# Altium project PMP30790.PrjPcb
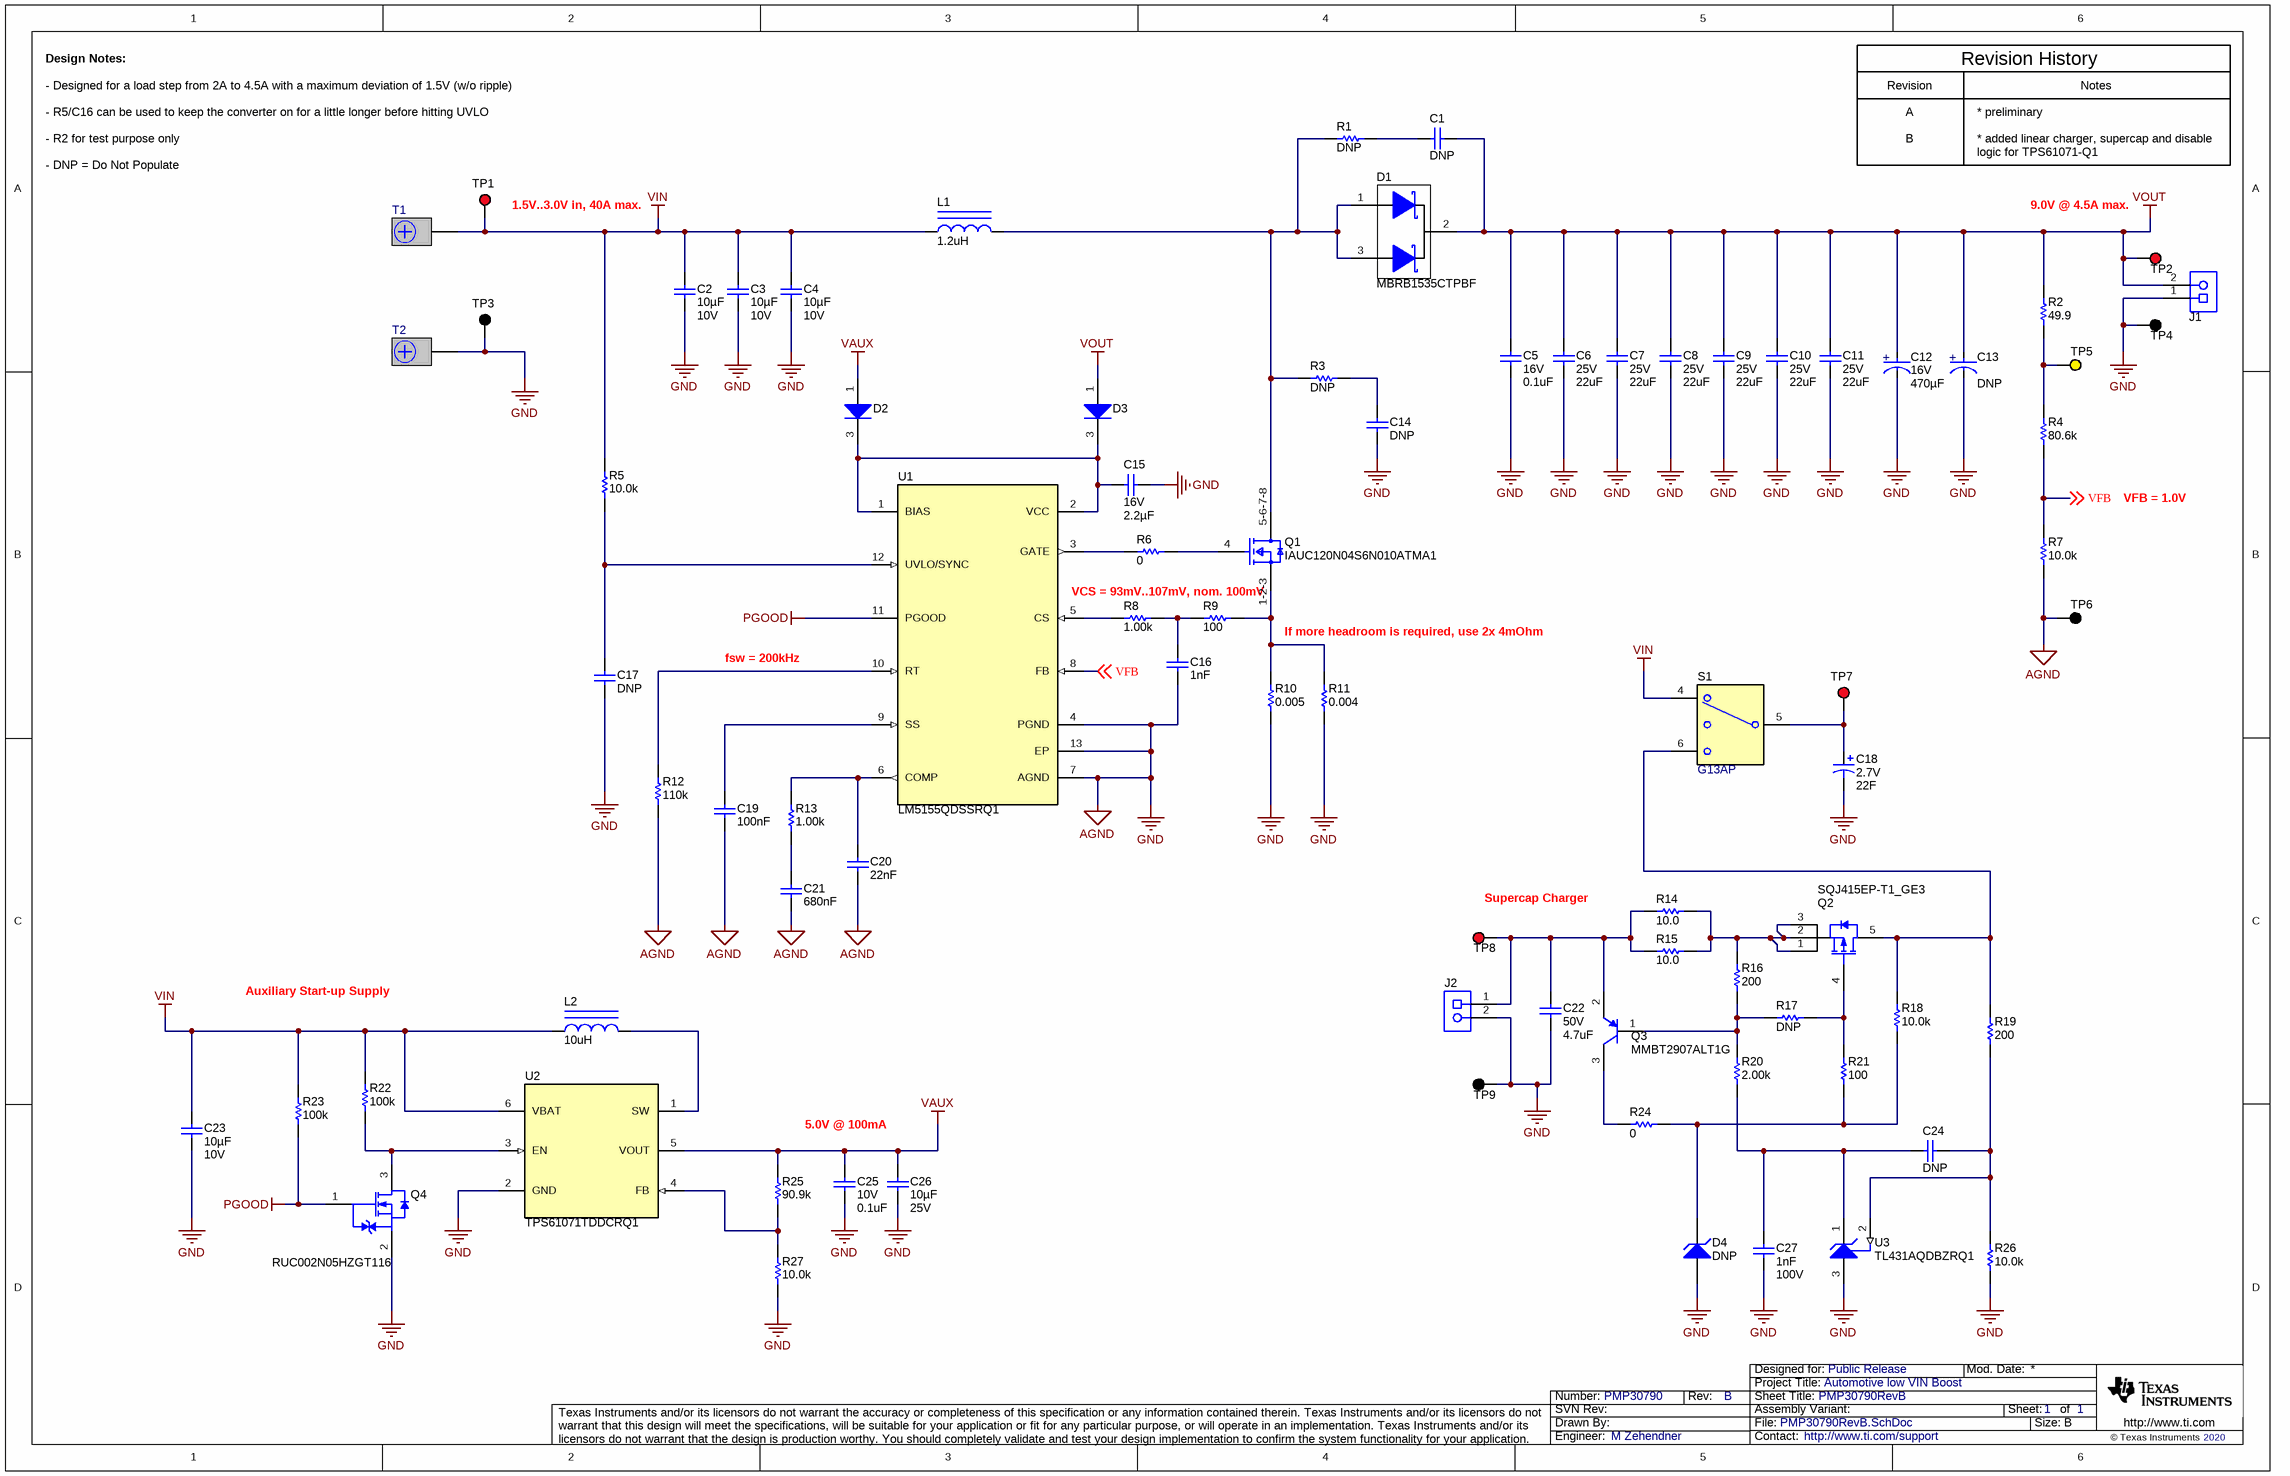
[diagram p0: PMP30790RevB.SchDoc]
CopyrightYear: 2020; PCB_Rev: A; PRJ_Customer: Public Release; PRJ_Engineer: M Zehendner; PRJ_Number: PMP30790; PRJ_Title: Automotive low VIN Boost; SCH_Rev: B; TechSupport: http://www.ti.com/support; TID: N/A
1 sheet, 81 parts. Net scope: global (net labels, ports and power ports of the same name join across sheets).
Board file: PMP30790_PCB.PcbDoc

## Sheet PMP30790RevB.SchDoc: PMP30790RevB
size 431 x 279 mm; DocumentNumber: 1; Revision: A; SheetNumber: 1; SheetTotal: 1; PageSetup: Record=PageOptions¦CenterHorizontal=True¦CenterVertical=True¦PrintScale=0.62¦XCorrection=1.00¦YCorrection=1.00¦PrintKind=0¦BorderSize=5000000¦LeftOffset=0¦BottomOffset=0¦Orientation=2¦PaperLength=1000¦PaperWidth=1000¦Scale=100¦PaperSource=15¦PrintQuality=600¦MediaType=1¦DitherType=10¦PaperKind=Letter (8.5 x 11")¦PrintScaleMode=1

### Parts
C1  Cap_F: DNP  [0805_HV]  (hidden comment: GRM21AR72E102KW01D)
C2  Cap_F: 10µF  VDC_V: 10V  [0603]  (hidden comment: GRM188Z71A106MA73D)
C3  Cap_F: 10µF  VDC_V: 10V  [0603]  (hidden comment: GRM188Z71A106MA73D)
C4  Cap_F: 10µF  VDC_V: 10V  [0603]  (hidden comment: GRM188Z71A106MA73D)
C5  VDC_V: 16V  ValueDisplayed: 0.1uF  [0402]  (hidden comment: GRM155R71C104JA88D)
C6  VDC_V: 25V  ValueDisplayed: 22uF  [1210_270]  (hidden comment: GRM32ER71E226KE15L)
C7  VDC_V: 25V  ValueDisplayed: 22uF  [1210_270]  (hidden comment: GRM32ER71E226KE15L)
C8  VDC_V: 25V  ValueDisplayed: 22uF  [1210_270]  (hidden comment: GRM32ER71E226KE15L)
C9  VDC_V: 25V  ValueDisplayed: 22uF  [1210_270]  (hidden comment: GRM32ER71E226KE15L)
C10  VDC_V: 25V  ValueDisplayed: 22uF  [1210_270]  (hidden comment: GRM32ER71E226KE15L)
C11  VDC_V: 25V  ValueDisplayed: 22uF  [1210_270]  (hidden comment: GRM32ER71E226KE15L)
C12  VDC_V: 16V  Cap_F: 470µF  [FP-HHXB160ARA471MJA0G_RADIAL-MFG]  (hidden comment: HHXB160ARA471MJA0G)
C13  Cap_F: DNP  [FP-HHXB160ARA471MJA0G_RADIAL-MFG]  (hidden comment: HHXB160ARA471MJA0G)
C14  Cap_F: DNP  [0805_HV]  (hidden comment: GRM21AR72E102KW01D)
C15  VDC_V: 16V  Cap_F: 2.2µF  [0603]  (hidden comment: GRM188Z71C225KE43)
C16  Cap_F: 1nF  [0603]  (hidden comment: GRM188R71C102KA01D)
C17  Cap_F: DNP  [0603]  (hidden comment: GRM188R71C104KA01D)
C18  VDC_V: 2.7V  ValueDisplayed: 22F  [JUM_1600x3150]  (hidden comment: JUMT1226MHD)
C19  Cap_F: 100nF  [0603]  (hidden comment: GRM188R71C104KA01D)
C20  Cap_F: 22nF  [0603]  (hidden comment: GRM188R71H223KA01D)
C21  Cap_F: 680nF  [0603]  (hidden comment: GRM188R71A684KA61D)
C22  VDC_V: 50V  ValueDisplayed: 4.7uF  [1210_270]  (hidden comment: GRM32ER71H475KA88L)
C23  Cap_F: 10µF  VDC_V: 10V  [0603]  (hidden comment: GRM188Z71A106MA73D)
C24  Cap_F: DNP  [0603]  (hidden comment: GRM188R72A102KA01D)
C25  VDC_V: 10V  ValueDisplayed: 0.1uF  [0402]  (hidden comment: GRM155R71A104KA01D)
C26  Cap_F: 10µF  VDC_V: 25V  [0805_HV]  (hidden comment: GRM21BZ71E106KE15L)
C27  Cap_F: 1nF  VDC_V: 100V  [0603]  (hidden comment: GRM188R72A102KA01D)
D1  MBRB1535CTPBF  [DDPAK]
D2  BAS16LT1G  [SOT-23]  (value not drawn)
D3  BAS16LT1G  [SOT-23]  (value not drawn)
D4  DNP  [SOD-523]
J1  691 101 710 002  [Wurth_691101710002]  (value not drawn)
J2  691 101 710 002  [Wurth_691101710002]  (value not drawn)
L1  ValueDisplayed: 1.2uH  [XAL1060]  (hidden comment: XAL1060-122MEB)
L2  ValueDisplayed: 10uH  [LPS4018]  (hidden comment: LPS4018-103MRB)
Q1  IAUC120N04S6N010ATMA1  [FP-IAUC120N04S6N009ATMA1_TDSON8-MFG]
Q2  SQJ415EP-T1_GE3  [PowerPAK_SO-8L]
Q3  MMBT2907ALT1G  [SOT-23]
Q4  RUC002N05HZGT116  [SOT-23_Rohm]
R1  ValueDisplayed: DNP  [1206]  (hidden comment: CRCW12061R00JNEA)
R2  ValueDisplayed: 49.9  [0603]  (hidden comment: CRCW060349R9FKEA)
R3  ValueDisplayed: DNP  [1206]  (hidden comment: CRCW12061R00JNEA)
R4  ValueDisplayed: 80.6k  [0603]  (hidden comment: CRCW060380K6FKEA)
R5  ValueDisplayed: 10.0k  [0603]  (hidden comment: CRCW060310K0FKEA)
R6  ValueDisplayed: 0  [0603]  (hidden comment: CRCW06030000Z0EA)
R7  ValueDisplayed: 10.0k  [0603]  (hidden comment: CRCW060310K0FKEA)
R8  ValueDisplayed: 1.00k  [0603]  (hidden comment: CRCW06031K00FKEA)
R9  ValueDisplayed: 100  [0603]  (hidden comment: CRCW0603100RFKEA)
R10  ValueDisplayed: 0.005  [2512]  (hidden comment: CSNL2512FT5L00)
R11  ValueDisplayed: 0.004  [2512]  (hidden comment: CSNL2512FT4L00)
R12  ValueDisplayed: 110k  [0603]  (hidden comment: CRCW0603110KFKEA)
R13  ValueDisplayed: 1.00k  [0603]  (hidden comment: CRCW06031K00FKEA)
R14  ValueDisplayed: 10.0  [1206]  (hidden comment: CRCW120610R0FKEA)
R15  ValueDisplayed: 10.0  [1206]  (hidden comment: CRCW120610R0FKEA)
R16  ValueDisplayed: 200  [0603]  (hidden comment: CRCW0603200RFKEA)
R17  ValueDisplayed: DNP  [0603]  (hidden comment: CRCW06030000Z0EA)
R18  ValueDisplayed: 10.0k  [0603]  (hidden comment: CRCW060310K0FKEA)
R19  ValueDisplayed: 200  [0603]  (hidden comment: CRCW0603200RFKEA)
R20  ValueDisplayed: 2.00k  [0603]  (hidden comment: CRCW06032K00FKEA)
R21  ValueDisplayed: 100  [0603]  (hidden comment: CRCW0603100RFKEA)
R22  ValueDisplayed: 100k  [0603]  (hidden comment: CRCW0603100KJNEA)
R23  ValueDisplayed: 100k  [0603]  (hidden comment: CRCW0603100KJNEA)
R24  ValueDisplayed: 0  [0603]  (hidden comment: CRCW06030000Z0EA)
R25  ValueDisplayed: 90.9k  [0402]  (hidden comment: CRCW040290K9FKED)
R26  ValueDisplayed: 10.0k  [0603]  (hidden comment: CRCW060310K0FKEA)
R27  ValueDisplayed: 10.0k  [0402]  (hidden comment: CRCW040210K0FKED)
S1  G13AP  [SW_G1xAP]
T1  CB35-36-CY  [CB35-36-CY]  (value not drawn)
T2  CB35-36-CY  [CB35-36-CY]  (value not drawn)
TP1  5010  [Keystone5010]  (value not drawn)
TP2  5010  [Keystone5010]  (value not drawn)
TP3  5011  [Keystone5011]  (value not drawn)
TP4  5011  [Keystone5011]  (value not drawn)
TP5  5014  [Keystone5014]  (value not drawn)
TP6  5011  [Keystone5011]  (value not drawn)
TP7  5010  [Keystone5010]  (value not drawn)
TP8  5010  [Keystone5010]  (value not drawn)
TP9  5011  [Keystone5011]  (value not drawn)
U1  LM5155QDSSRQ1  [DSS0012C]
U2  TPS61071TDDCRQ1  [DDC0006A_N]
U3  TL431AQDBZRQ1  [DBZ0003A_N]

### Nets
AGND: C2.2 C3.2 C4.2 C5.2 C6.2 C7.2 C8.2 C9.2 C10.2 C11.2 C12.1(CATHODE) C13.1(CATHODE) C14.2 C15.2 C16.2 C17.2 C18.2(-) C19.2 C20.2 C21.2 C22.2 C23.2 C25.2 C26.2 C27.2 D4.2(A) J1.1 J2.2 Q4.2(S) R7.1 R10.1 R11.1 R12.1 R26.1 R27.1 T2.1 TP3.1 TP4.1 TP6.1 TP9.1 U1.4(PGND) U1.7(AGND) U1.13(EP) U2.2(GND) U3.3(ANODE)  [also labelled GND]
PGOOD: Q4.1(G) R23.1 U1.11(PGOOD)
VAUX: C25.1 C26.1 D2.1(A) R25.2 U2.5(VOUT)
VIN: C2.1 C3.1 C4.1 C23.1 L1.1 L2.1 R5.2 R22.2 R23.2 S1.4 T1.1 TP1.1 U2.6(VBAT)
VOUT: C1.1 C5.1 C6.1 C7.1 C8.1 C9.1 C10.1 C11.1 C12.2(ANODE) C13.2(ANODE) D1.2(K) D3.1(A) J1.2 R2.2 TP2.1
VFB: R4.1 R7.2 U1.8(FB) ; off-sheet VFB
NetC1_2: C1.2 R1.2
NetC14_1: C14.1 R3.2
NetC15_1: C15.1 D2.3(K) D3.3(K) U1.1(BIAS) U1.2(VCC)
NetC16_1: C16.1 R8.2 R9.1
NetC17_1: C17.1 R5.1 U1.12(UVLO/SYNC)
NetC18_1: C18.1(+) S1.5(COM) TP7.1
NetC19_1: C19.1 U1.9(SS)
NetC20_1: C20.1 R13.2 U1.6(COMP)
NetC21_1: C21.1 R13.1
NetC22_1: C22.1 J2.1 Q3.2(E) R14.1 R15.1 TP8.1
NetC24_1: C24.1 C27.1 R20.1 U3.1(CATHODE)
NetC24_2: C24.2 R19.1 R26.2 U3.2(REF)
NetD1_1: D1.1(A) D1.3(A) L1.2 Q1.5-6-7-8(D) R1.1 R3.1
NetD4_1: D4.1(K) R18.1 R21.1 R24.2
NetL2_2: L2.2 U2.1(SW)
NetQ1_1-2-3: Q1.1-2-3(S) R9.2 R10.2 R11.2
NetQ1_4: Q1.4(G) R6.2
NetQ2_1: Q2.1(S) Q2.2(S) Q2.3(S) R14.2 R15.2 R16.2
NetQ2_4: Q2.4(G) R17.2 R21.2
NetQ2_5: Q2.5(D) R18.2 R19.2 S1.6
NetQ3_1: Q3.1(B) R16.1 R17.1 R20.2
NetQ3_3: Q3.3(C) R24.1
NetQ4_3: Q4.3(D) R22.1 U2.3(EN)
NetR2_1: R2.1 R4.2 TP5.1
NetR6_1: R6.1 U1.3(GATE)
NetR8_1: R8.1 U1.5(CS)
NetR12_2: R12.2 U1.10(RT)
NetR25_1: R25.1 R27.2 U2.4(FB)

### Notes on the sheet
- Design Notes:
- - Designed for a load step from 2A to 4.5A with a maximum deviation of 1.5V (w/o ripple)
- Revision
- Revision History
- Notes
- - DNP = Do Not Populate
- - R5/C16 can be used to keep the converter on for a little longer before hitting UVLO
- - R2 for test purpose only
- A
- B
- * preliminary
- * added linear charger, supercap and disable
- logic for TPS61071-Q1
- (near TP1) 1.5V..3.0V in, 40A max.
- (near TP2) 9.0V @ 4.5A max.
- VFB = 1.0V
- VCS = 93mV..107mV, nom. 100mV
- If more headroom is required, use 2x 4mOhm
- fsw = 200kHz
- (near TP8) Supercap Charger
- Auxiliary Start-up Supply
- 5.0V @ 100mA

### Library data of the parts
C1 C14 = CMP-0008251-2: CAP, CERM, 1000 pF, 250 V, +/- 10%, X7R, 0805; Manufacturer: MuRata; TaMin_C: -55°C; Polarized: N; SizeAreaWB_mm2: 6.75; Value1: Unknown; U/M: EA; Value: 1000pF; TaMax_C: 125°C; SizeZ_mm: 1.45; SizeX_mm: 2; SizeY_mm: 1.25; Cap_Case: 0805; Value2: 250V; SizeArea_mm2: 2.5; AEC Category: Q200
C2-C4 C23 = CMP-0007497-5: CAP, CERM, 10 uF, 10 V, +/- 20%, X7R, 0603; Manufacturer: MuRata; TaMin_C: -55°C; Polarized: N; SizeAreaWB_mm2: 4.68; Value1: Unknown; U/M: EA; Value: 10uF; TaMax_C: 125°C; SizeZ_mm: 1; SizeX_mm: 1.6; SizeY_mm: 0.8; SizeArea_mm2: 1.28; AEC Category: Q200
C5 = CMP-0006640-2: CAP, CERM, 0.1 uF, 16 V, +/- 5%, X7R, 0402; Manufacturer: MuRata; TaMin_C: -55°C; Polarized: N; SizeAreaWB_mm2: 3; Value1: Unknown; U/M: EA; Value: 0.1uF; TaMax_C: 125°C; SizeZ_mm: 0.6; SizeX_mm: 1; SizeY_mm: 0.5; Cap_F: 100nF; AEC Category: Q200
C6-C11 = CMP-0009224-2: CAP, CERM, 22 uF, 25 V, +/- 10%, X7R, 1210; Manufacturer: MuRata; TaMin_C: -55°C; Polarized: N; SizeAreaWB_mm2: 14.7; Value1: Unknown; U/M: EA; Value: 22uF; TaMax_C: 125°C; SizeZ_mm: 2.7; SizeX_mm: 3.2; SizeY_mm: 2.5; Cap_Case: 1210; SizeArea_mm2: 8; Cap_F: 22µF; AEC Category: Q200
C12 = CMP-0086437-1: Cap Aluminum Polymer 470uF 16VDC 20% (10 X 10mm) SMD 0.018 Ohm 2600mA 5000h 105C Automotive T/R; Manufacturer: United Chemi-Con; AEC Qualified: Yes; SizeZ_mm: 10.3mm; IRMS_A: 2.6A; Symbol Name: SYM-HHXB160ARA471MJA0G; AEC Grade: Grade 2
C13 = CMP-0086437-1: Cap Aluminum Polymer 470uF 16VDC 20% (10 X 10mm) SMD 0.018 Ohm 2600mA 5000h 105C Automotive T/R; Manufacturer: United Chemi-Con; VDC_V: 16V; AEC Qualified: Yes; SizeZ_mm: 10.3mm; IRMS_A: 2.6A; Symbol Name: SYM-HHXB160ARA471MJA0G; AEC Grade: Grade 2
C15 = CMP-0007499-4: CAP, CERM, 2.2 uF, 16 V, +/- 10%, X7R, 0603; Manufacturer: MuRata; TaMin_C: -55°C; Polarized: N; SizeAreaWB_mm2: 4.68; Value1: Unknown; U/M: EA; Value: 2.2uF; TaMax_C: 125°C; SizeZ_mm: 1; SizeX_mm: 1.6; SizeY_mm: 0.8; SizeArea_mm2: 1.28; AEC Category: Q200
C16 = CMP-0007376-4: CAP, CERM, 1000 pF, 16 V, +/- 10%, X7R, 0603; Manufacturer: MuRata; TaMin_C: -55°C; Polarized: N; SizeAreaWB_mm2: 4.68; Value1: Unknown; U/M: EA; Value: 1000pF; TaMax_C: 125°C; SizeZ_mm: 1; SizeX_mm: 1.6; SizeY_mm: 0.8; Value2: 16V; SizeArea_mm2: 1.28; AEC Category: Q200
C17 C19 = CMP-0007378-5: CAP, CERM, 0.1 uF, 16 V, +/- 10%, X7R, 0603; Manufacturer: MuRata; TaMin_C: -55°C; Polarized: N; SizeAreaWB_mm2: 4.68; Value1: Unknown; U/M: EA; Value: 0.1uF; TaMax_C: 125°C; SizeZ_mm: 1; SizeX_mm: 1.6; SizeY_mm: 0.8; Value2: 16V; SizeArea_mm2: 1.28; AEC Category: Q200
C18 = CMP-0084050-1: CAP, Electric Double Layer, 22000000 µF, 2.7 V,+/- 20%, 0.07 ohm, TH; Manufacturer: Nichicon; TaMin_C: -25°C; ESR_ohm: 0.07; Polarized: Y; SizeAreaWB_mm2: 324; Value: 22000000uF; TaMax_C: 70°C; SizeZ_mm: 33.5; SizeX_mm: 16; Cap_Case: 16x31.5mm; SizeArea_mm2: 256; CompType: Capacitor; AEC Qualified: N; AEC Category: Q200
C20 = CMP-0007444-4: CAP, CERM, 0.022 uF, 50 V, +/- 10%, X7R, 0603; Manufacturer: MuRata; TaMin_C: -55°C; Polarized: N; SizeAreaWB_mm2: 4.68; Value1: Unknown; U/M: EA; TaMax_C: 125°C; SizeZ_mm: 1; SizeX_mm: 1.6; SizeY_mm: 0.8; Value2: 50V; SizeArea_mm2: 1.28; AEC Category: Q200
C21 = CMP-0007375-4: CAP, CERM, 0.68 uF, 10 V, +/- 10%, X7R, 0603; Manufacturer: MuRata; TaMin_C: -55°C; Polarized: N; SizeAreaWB_mm2: 4.68; Value1: Unknown; U/M: EA; Value: 0.68uF; TaMax_C: 125°C; SizeZ_mm: 1; SizeX_mm: 1.6; SizeY_mm: 0.8; Value2: 10V; SizeArea_mm2: 1.28; AEC Category: Q200
C22 = CMP-0009228-2: CAP, CERM, 4.7 uF, 50 V, +/- 10%, X7R, 1210; Manufacturer: MuRata; TaMin_C: -55°C; ESR_ohm: 2m; Polarized: N; SizeAreaWB_mm2: 14.7; Value1: 0.002 ohm; U/M: EA; Value: 4.7uF; TaMax_C: 125°C; SizeZ_mm: 2.7; SizeX_mm: 3.2; SizeY_mm: 2.5; Cap_Case: 1210; SizeArea_mm2: 8; Cap_F: 4.7µF; AEC Category: Q200
C24 = CMP-0007467-4: CAP, CERM, 1000 pF, 100 V, +/- 10%, X7R, 0603; Manufacturer: MuRata; TaMin_C: -55°C; Polarized: N; SizeAreaWB_mm2: 4.68; Value1: Unknown; U/M: EA; Value: 1000pF; TaMax_C: 125°C; SizeZ_mm: 1; SizeX_mm: 1.6; SizeY_mm: 0.8; Value2: 100V; SizeArea_mm2: 1.28; AEC Category: Q200
C25 = CMP-0006629-2: CAP, CERM, 0.1 uF, 10 V, +/- 10%, X7R, 0402; Manufacturer: MuRata; TaMin_C: -55°C; Polarized: N; SizeAreaWB_mm2: 3; Value1: Unknown; U/M: EA; Value: 0.1uF; TaMax_C: 125°C; SizeZ_mm: 0.6; SizeX_mm: 1; SizeY_mm: 0.5; Cap_F: 100nF; AEC Category: Q200
C26 = CMP-0008378-2: CAP, CERM, 10 uF, 25 V, +/- 10%, X7R, 0805; Manufacturer: MuRata; TaMin_C: -55°C; Polarized: N; SizeAreaWB_mm2: 6.75; Value1: Unknown; U/M: EA; Value: 10uF; TaMax_C: 125°C; SizeZ_mm: 1.45; SizeX_mm: 2; SizeY_mm: 1.25; Cap_Case: 0805; SizeArea_mm2: 2.5; AEC Category: Q200
C27 = CMP-0007467-4: CAP, CERM, 1000 pF, 100 V, +/- 10%, X7R, 0603; Manufacturer: MuRata; TaMin_C: -55°C; Polarized: N; SizeAreaWB_mm2: 4.68; Value1: Unknown; U/M: EA; Value: 1000pF; TaMax_C: 125°C; SizeZ_mm: 1; SizeX_mm: 1.6; SizeY_mm: 0.8; SizeArea_mm2: 1.28; AEC Category: Q200
D1 = CMP-0028556-3: Diode, Schottky, 35 V, 15 A, DDPAK; Manufacturer: International Rectifier; Io_A: 15A; SizeX_mm: 15.245; Green_REACh: Incomplete; SizeArea_mm2: 154.8892; SizeZ_mm: 4.445; TJmax_C: 150°C; RJC_CperW: 3; Value: 35V; Vf_V: 800mV; Green_Lifecycle: Not Set; AEC Category: Q101; SizeY_mm: 10.16; Value2: 0.8V; SizeAreaWB_mm2: 209.6992
D2 D3 = CMP-0029193-2: Diode, Switching, 100 V, 0.2 A, SOT-23; Manufacturer: ON Semiconductor; Value: 100V; Green_Lifecycle: Active; SizeAreaWB_mm2: 14; Vf_V: 1.25V; SizeZ_mm: 1.1; AEC Qualified: N; SizeX_mm: 2.5; Green_REACh: Passed; AEC Category: Q101; Value1: 0.2A; SizeY_mm: 3; SizeArea_mm2: 7.5; Io_A: 200mA; TJmax_C: 150°C
D4 = CMP-0005892-4: Diode, Zener, 2.7 V, 300 mW, SOD-523; Manufacturer: Diodes Inc.; PartNumber: BZT52C2V7T-7; Value: 2.7V; SizeY_mm: 0.9; AEC Category: Q101; SizeX_mm: 1.7; Power_W: 300mW; Value1: 0.3W; SizeZ_mm: 0.65; SizeAreaWB_mm2: 5.13; RJA_CperW: 417; SizeArea_mm2: 1.53
J1 J2 = CMP-0054828-1: Terminal Block, 5 mm, 2x1, Tin, TH; Manufacturer: Wurth Elektronik; CNHeader: FALSE; Green_Lifecycle: Active; Green_REACh: Passed; CT: TRUE
L1 = CMP-0060959-1: Inductor, Shielded, Composite, 1.2 uH, 26.3 A, 0.0025 ohm, AEC-Q200 Grade 1, SMD; Manufacturer: Coilcraft; Isat: 43A @ 30% inductance drop; Irms: 26.3A @ 40C rise; Green_Lifecycle: Not Set; SizeAreaWB_mm2: 159.6; DCR_ohm: 2.5m; Green_REACh: Incomplete; Value: 1.2uH; Imax_A: 26.3A; SizeZ_mm: 6; SizeX_mm: 11.3; SizeY_mm: 10; SizeArea_mm2: 113; Ind_H: 1.2µH; AEC Qualified: Y; AEC Grade: 1; AEC Category: Q200
L2 = CMP-0060471-1: Inductor, Shielded Drum Core, Ferrite, 10 uH, 1.25 A, 0.18 ohm, SMD; Manufacturer: Coilcraft; Isat: 1.3A @ 30% inductance drop; Irms: 1.25A @ 40C rise; Green_Lifecycle: Not Set; SizeAreaWB_mm2: 24.01; DCR_ohm: 0.18; Green_REACh: Incomplete; Value: 10uH; Imax_A: 1.25A; SizeZ_mm: 1.7; SizeX_mm: 3.9; SizeArea_mm2: 15.21; Ind_H: 10µH; AEC Qualified: N; AEC Category: Q200
Q1 = CMP-0086959-1: Trans Mosfet N-ch 40V 120A 8-PIN Pg-tdson T/R; Manufacturer: Infineon; SizeZ_mm: 1.1mm; Symbol Name: SYM-IAUC120N04S6N010ATMA1; Rdson45_ohm: 930µ; QgTyp_nC: 81nC @ 10V; Vgs_V: 20V; AEC Qualified: Yes; ChMode: False
Q2 = CMP-0083987-2: MOSFET, P-CH, -40 V, -30 A, AEC-Q101, PowerPAK_SO-8L; Alternate Manufacturer: None; Manufacturer: Vishay-Semiconductor; Rdson45_ohm: 0.024; QgTyp_nC: 73; Value: -60V; ChMode: Enhancement; SizeAreaWB_mm2: 58.1095; Value1: 0.024 ohm; SizeZ_mm: 1.14; SizeArea_mm2: 31.5495; ChType: P; SizeY_mm: 5.13; AEC Qualified: Y; AEC Category: Q101; IdsMax_A: -52A; SizeX_mm: 6.15; Vgs_V: 20V; Value2: 73 nC
Q3 = CMP-0000344-2: Transistor, PNP, 60 V, 0.6 A, SOT-23; Manufacturer: ON Semiconductor; TaMax_C: 150°C; Value1: 0.6 A; Vcesat1_V: 1.6V; SizeX_mm: 2.5; SizeY_mm: 3; TaMin_C: -55°C; IcRated_A: 600mA; CompType: BJT; SizeZ_mm: 1.1; Value: 60 V; SizeArea_mm2: 7.5; NPN: 0; Vceo_V: 60V; PNP: 1; AEC Category: Q101; SizeAreaWB_mm2: 14; U/M: EA
Q4 = CMP-0085604-2: MOSFET, N-CH, 50 V, 0.2 A, AEC-Q101, SOT-23; Manufacturer: Rohm; Alternate Manufacturer: None; Value1: 2.2 ohm; Value: 50V; SizeX_mm: 2.4; SizeZ_mm: 0.95; AEC Qualified: Y; SizeAreaWB_mm2: 13.26; SizeY_mm: 2.9; Vgs_V: 8V; SizeArea_mm2: 6.96; Value2: ? nC; ChType: N; AEC Category: Q101; Rdson45_ohm: 2.2; ChMode: Enhancement; IdsMax_A: 200mA
R1 R3 = CMP-0018617-3: RES, 1.0, 5%, 0.25 W, AEC-Q200 Grade 0, 1206; Manufacturer: Vishay-Dale; Power_W: 250mW; TempCo: 200 ppm/C; Value_Code: 1R00; Value: 1.0; EIA_Code: E24; Res_ohm: 1; SizeX_mm: 3.2; SizeY_mm: 1.6; SizeZ_mm: 1.35; Value2: 0.25W; SizeArea_mm2: 5.12; AEC Qualified: Y; VDC_V: 200V; AEC Category: Q200; AEC Grade: 0
R2 = CMP-0022448-4: RES, 49.9, 1%, 0.1 W, AEC-Q200 Grade 0, 0603; Manufacturer: Vishay-Dale; Power_W: 100mW; TempCo: 100 ppm/C; Value_Code: 49R9; Value: 49.9; EIA_Code: E96; SizeX_mm: 1.6; SizeY_mm: 0.8; SizeZ_mm: 1; Value2: 0.1W; SizeArea_mm2: 1.28; AEC Qualified: Y; VDC_V: 75V; AEC Category: Q200; AEC Grade: 0
R4 = CMP-0022616-4: RES, 80.6 k, 1%, 0.1 W, AEC-Q200 Grade 0, 0603; Manufacturer: Vishay-Dale; Power_W: 100mW; TempCo: 100 ppm/C; Value_Code: 80k6; Value: 80.6k; EIA_Code: E96; SizeX_mm: 1.6; SizeY_mm: 0.8; SizeZ_mm: 1; Value2: 0.1W; SizeArea_mm2: 1.28; AEC Qualified: Y; VDC_V: 75V; AEC Category: Q200; AEC Grade: 0
R5 R7 R18 R26 = CMP-0021998-4: RES, 10.0 k, 1%, 0.1 W, AEC-Q200 Grade 0, 0603; Manufacturer: Vishay-Dale; Power_W: 100mW; TempCo: 100 ppm/C; Value_Code: 10k0; Value: 10.0k; EIA_Code: E96; Res_ohm: 10k; SizeX_mm: 1.6; SizeY_mm: 0.8; SizeZ_mm: 1; Value2: 0.1W; SizeArea_mm2: 1.28; AEC Qualified: Y; VDC_V: 75V; AEC Category: Q200; AEC Grade: 0
R6 R17 R24 = CMP-0025697-1: RES, 0, 5%, 0.1 W, 0603; Manufacturer: Vishay-Dale; Power_W: 100mW; TempCo: 200 ppm/C; Value_Code: 0000; U/M: EA; Value: 0; EIA_Code: E24; SizeX_mm: 1.6; SizeY_mm: 0.8; SizeZ_mm: 1; Value2: 0.1W; SizeArea_mm2: 1.28; VDC_V: 75V; AEC Category: Q200
R8 R13 = CMP-0022109-5: RES, 1.00 k, 1%, 0.1 W, AEC-Q200 Grade 0, 0603; Manufacturer: Vishay-Dale; Power_W: 100mW; TempCo: 100 ppm/C; Value_Code: 1k00; Value: 1.00k; EIA_Code: E96; Res_ohm: 1k; SizeX_mm: 1.6; SizeY_mm: 0.8; SizeZ_mm: 1; Value2: 0.1W; SizeArea_mm2: 1.28; AEC Qualified: Y; VDC_V: 75V; AEC Category: Q200; AEC Grade: 0
R9 R21 = CMP-0021991-4: RES, 100, 1%, 0.1 W, AEC-Q200 Grade 0, 0603; Manufacturer: Vishay-Dale; Power_W: 100mW; TempCo: 100 ppm/C; Value_Code: 100R; Value: 100; EIA_Code: E96; SizeX_mm: 1.6; SizeY_mm: 0.8; SizeZ_mm: 1; Value2: 0.1W; SizeArea_mm2: 1.28; AEC Qualified: Y; VDC_V: 75V; AEC Category: Q200; AEC Grade: 0
R10 = CMP-0015758-2: RES, 0.005, 1%, 2 W, 2512; Manufacturer: Stackpole Electronics Inc; Power_W: 2W; TempCo: 50 ppm/C; Value_Code: 5L000; U/M: EA; Value: 0.005; EIA_Code: E96; Res_ohm: 5m; SizeX_mm: 6.3; SizeY_mm: 3.2; SizeZ_mm: 0.71; SizeArea_mm2: 20.16; AEC Category: Q200
R11 = CMP-0015757-2: RES, 0.004, 1%, 2 W, 2512; Manufacturer: Stackpole Electronics Inc; Power_W: 2W; TempCo: 50 ppm/C; Value_Code: 4L000; U/M: EA; Value: 0.004; Res_ohm: 4m; SizeX_mm: 6.3; SizeY_mm: 3.2; SizeZ_mm: 0.71; SizeArea_mm2: 20.16; VDC_V: 200V; AEC Category: Q200
R12 = CMP-0022008-4: RES, 110 k, 1%, 0.1 W, AEC-Q200 Grade 0, 0603; Manufacturer: Vishay-Dale; Power_W: 100mW; TempCo: 100 ppm/C; Value: 110k; EIA_Code: E96; SizeX_mm: 1.6; SizeY_mm: 0.8; SizeZ_mm: 1; Value2: 0.1W; SizeArea_mm2: 1.28; AEC Qualified: Y; VDC_V: 75V; AEC Category: Q200; AEC Grade: 0
R14 R15 = CMP-0016583-3: RES, 10.0, 1%, 0.25 W, AEC-Q200 Grade 0, 1206; Manufacturer: Vishay-Dale; Power_W: 250mW; TempCo: 100 ppm/C; Value_Code: 10R0; Value: 10.0; EIA_Code: E96; Res_ohm: 10; SizeX_mm: 3.2; SizeY_mm: 1.6; SizeZ_mm: 1.35; Value2: 0.25W; SizeArea_mm2: 5.12; AEC Qualified: Y; VDC_V: 200V; AEC Category: Q200; AEC Grade: 0
R16 R19 = CMP-0022201-5: RES, 200, 1%, 0.1 W, AEC-Q200 Grade 0, 0603; Manufacturer: Vishay-Dale; Power_W: 100mW; TempCo: 100 ppm/C; Value_Code: 200R; Value: 200; EIA_Code: E96; SizeX_mm: 1.6; SizeY_mm: 0.8; SizeZ_mm: 1; Value2: 0.1W; SizeArea_mm2: 1.28; AEC Qualified: Y; VDC_V: 75V; AEC Category: Q200; AEC Grade: 0
R20 = CMP-0022268-4: RES, 2.00 k, 1%, 0.1 W, AEC-Q200 Grade 0, 0603; Manufacturer: Vishay-Dale; Power_W: 100mW; TempCo: 100 ppm/C; Value_Code: 2k00; Value: 2.00k; EIA_Code: E96; Res_ohm: 2k; SizeX_mm: 1.6; SizeY_mm: 0.8; SizeZ_mm: 1; Value2: 0.1W; SizeArea_mm2: 1.28; AEC Qualified: Y; VDC_V: 75V; AEC Category: Q200; AEC Grade: 0
R22 R23 = CMP-0025698-4: RES, 100 k, 5%, 0.1 W, AEC-Q200 Grade 0, 0603; Manufacturer: Vishay-Dale; Power_W: 100mW; TempCo: 200 ppm/C; Value: 100k; EIA_Code: E24; SizeX_mm: 1.6; SizeY_mm: 0.8; SizeZ_mm: 1; Value2: 0.1W; SizeArea_mm2: 1.28; AEC Qualified: Y; VDC_V: 75V; AEC Category: Q200; AEC Grade: 0
R25 = CMP-0026605-2: RES, 90.9 k, 1%, 0.063 W, AEC-Q200 Grade 0, 0402; Manufacturer: Vishay-Dale; Power_W: 63mW; TempCo: 100 ppm/C; Value_Code: 90k9; Value: 90.9k; EIA_Code: E96; SizeX_mm: 1; SizeY_mm: 0.5; SizeZ_mm: 0.6; Value2: 0.063W; AEC Qualified: Y; VDC_V: 50V; AEC Category: Q200; AEC Grade: 0
R27 = CMP-0025958-3: RES, 10.0 k, 1%, 0.063 W, AEC-Q200 Grade 0, 0402; Manufacturer: Vishay-Dale; Power_W: 63mW; TempCo: 100 ppm/C; Value_Code: 10k0; Value: 10.0k; EIA_Code: E96; Res_ohm: 10k; SizeX_mm: 1; SizeY_mm: 0.5; SizeZ_mm: 0.6; Value2: 0.063W; AEC Qualified: Y; VDC_V: 50V; AEC Category: Q200; AEC Grade: 0
S1 = CMP-0002118-3: Switch, Toggle, SPDT 1Pos, TH; Manufacturer: NKK Switches; CurrentRating_mA: 400A; VDC_V: 28V; SwitchFunction: ON-OFF-ON; PositionCount: 1
T1 T2 = CMP-0055442-1: Terminal 50A Lug; Manufacturer: Panduit; CNHeader: FALSE; Green_Lifecycle: Not Set; Cert_CULUS: Y; Green_REACh: Incomplete; Voltage_V: 600V; CompType: Screw Terminal; ContactFinish: Copper
TP1 TP2 TP7 TP8 = CMP-0055147-1: Test Point, Multipurpose, Red, TH; Manufacturer: Keystone; CNHeader: FALSE; Green_Lifecycle: Active; Green_REACh: Passed; ContactFinish: Silver; CT: TRUE
TP3 TP4 TP6 TP9 = CMP-0055148-1: Test Point, Multipurpose, Black, TH; Manufacturer: Keystone; CNHeader: FALSE; Green_Lifecycle: Active; Green_REACh: Passed; ContactFinish: Silver; CT: TRUE
TP5 = CMP-0055151-1: Test Point, Multipurpose, Yellow, TH; Manufacturer: Keystone; CNHeader: FALSE; Green_Lifecycle: Active; Green_REACh: Passed; ContactFinish: Silver; CT: TRUE
U1 = CMP-0081539-1: Automotive Grade 2.2-MHz Wide Input Non-synchronous Boost Controller, DSS0012C (WSON-12); Alternate PartNumber: LM5155QDSSTQ1; Alternate Manufacturer: Texas Instruments; SizeAreaWB_mm2: 12; SizeZ_mm: 0.8; SizeX_mm: 2; SizeY_mm: 3; SizeArea_mm2: 6; CompType: IC; AEC Qualified: Y; AEC Category: Q200
U2 = CMP-0067186-2: Automotive Catalog Adjustable, 600-mA Switch, 90% Efficient PWM Boost Converter, DDC0006A (SOT-23-T-6); Manufacturer: Texas Instruments; SizeZ_mm: 0.87; SizeX_mm: 1.65; SizeY_mm: 2.95; SizeArea_mm2: 4.8675; CompType: IC; U/M: EA; SizeAreaWB_mm2: 10.4675
U3 = CMP-0033164-1: Automotive Catalog Adjustable Precision Shunt Regulator, 34 ppm / degC, 100 mA, -40 to 125 degC, 3-pin SOT-23 (DBZ), Green (RoHS & no Sb/Br); Manufacturer: Texas Instruments; SubFamily: Shunt Voltage Reference; Initial Accuracy @ 25/deg C(%): 1; Min Iz for Regulation(uA): 600; Iout/Iz(Max)(mA): 100; Temp Coeff(Typ)(ppm/ degree C): 34; VO Adj(Max)(V): 36; VO Adj(Min)(V): 2.495

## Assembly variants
001: not fitted FID1 FID2 FID3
